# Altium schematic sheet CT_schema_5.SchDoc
size 257 x 245 mm
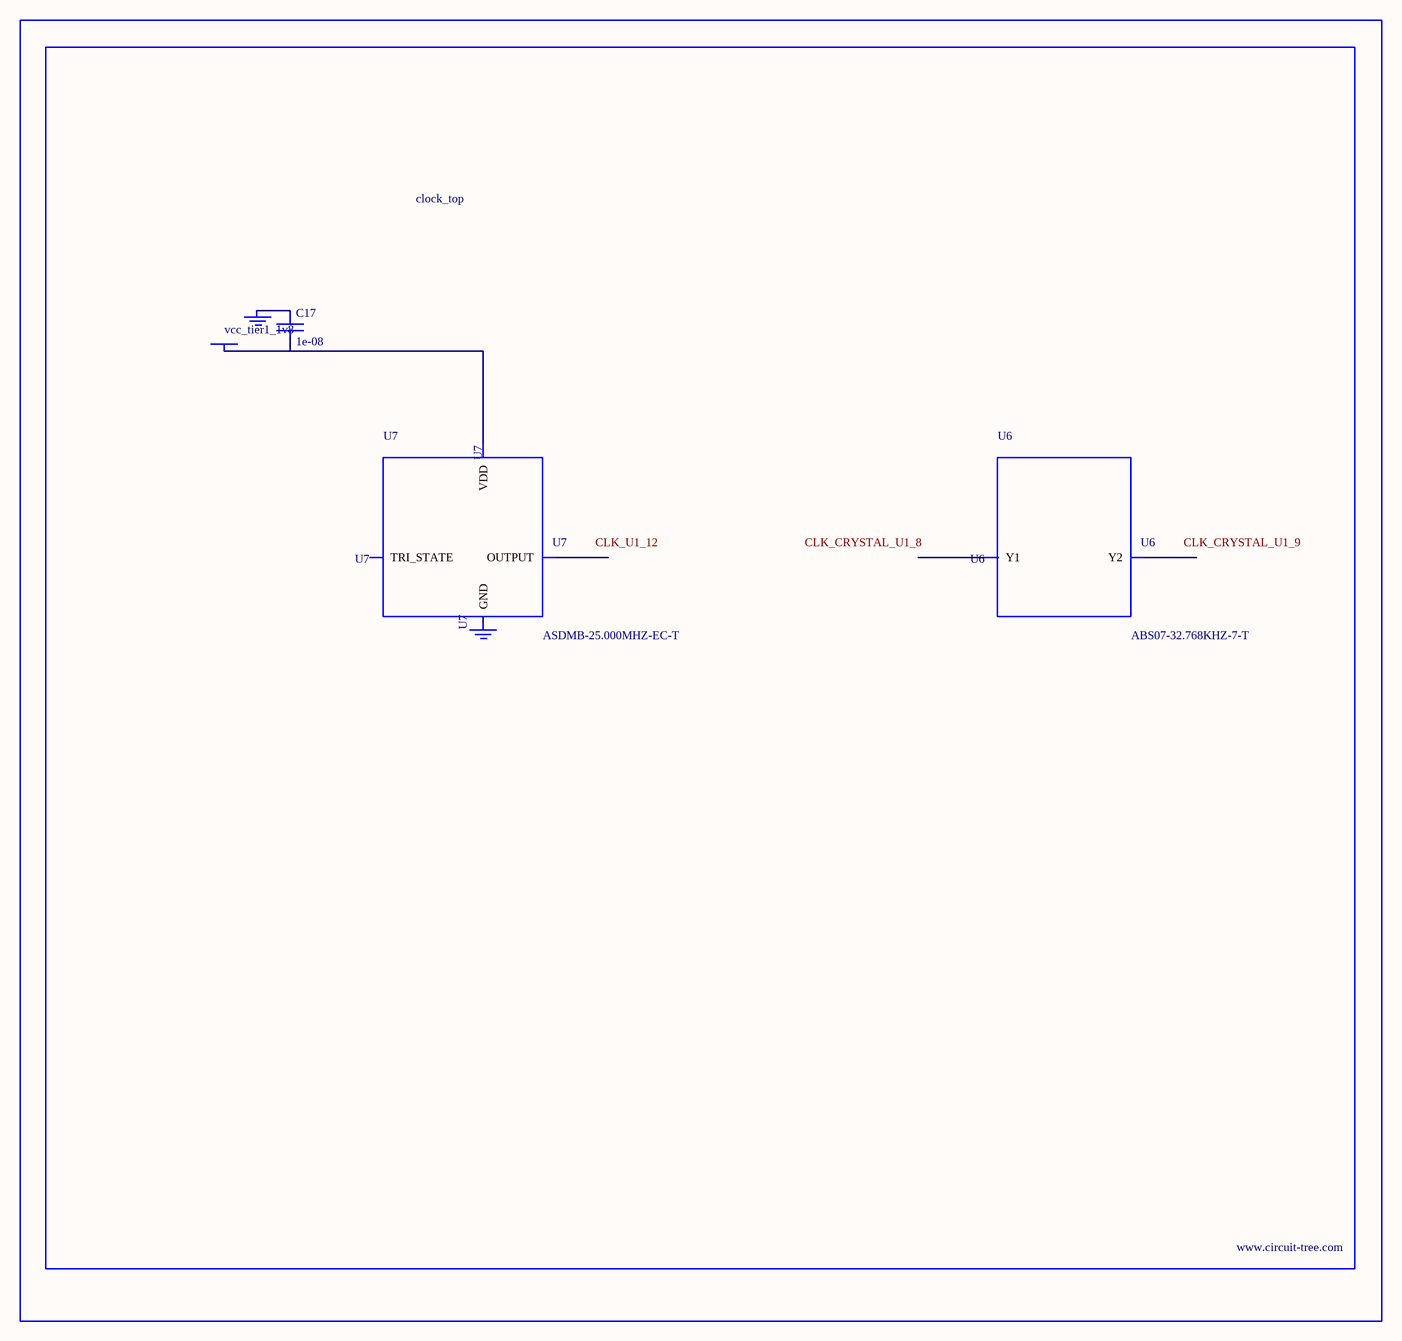
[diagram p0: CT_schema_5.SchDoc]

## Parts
BORDER4  (no value)
C17  1e-08  [C0402]
GND_INSTANCE_4_0  (no value)
GND_INSTANCE_4_1  (no value)
POWER_INSTANCE_4_0  vcc_tier1_1v8
U6  ABS07-32.768KHZ-7-T  [ABS07-32.768KHZ-7-T]
U7  ASDMB-25.000MHZ-EC-T  [ASDMB-XX.XXXXMHZ-XX-XX-XXX]

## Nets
NetC17_1: C17.1 GND_INSTANCE_4_0.0(GND)
NetC17_2: C17.2 POWER_INSTANCE_4_0.0(PWR) U7.4(VDD)

Not connected (* = marked no-connect by the designer): GND_INSTANCE_4_1 0(GND); U6 1(Y1) 2(Y2); U7 1(TRI_STATE) 2(GND) 3(OUTPUT)

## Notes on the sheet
- Labels drawn without touching a wire or pin: CLK_CRYSTAL_U1_8, CLK_CRYSTAL_U1_9, CLK_U1_12

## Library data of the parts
BORDER4 = BORDER_PAGE4
C17 = C0402C103K3RAC
GND_INSTANCE_4_0 GND_INSTANCE_4_1 = GND
POWER_INSTANCE_4_0 = PWR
